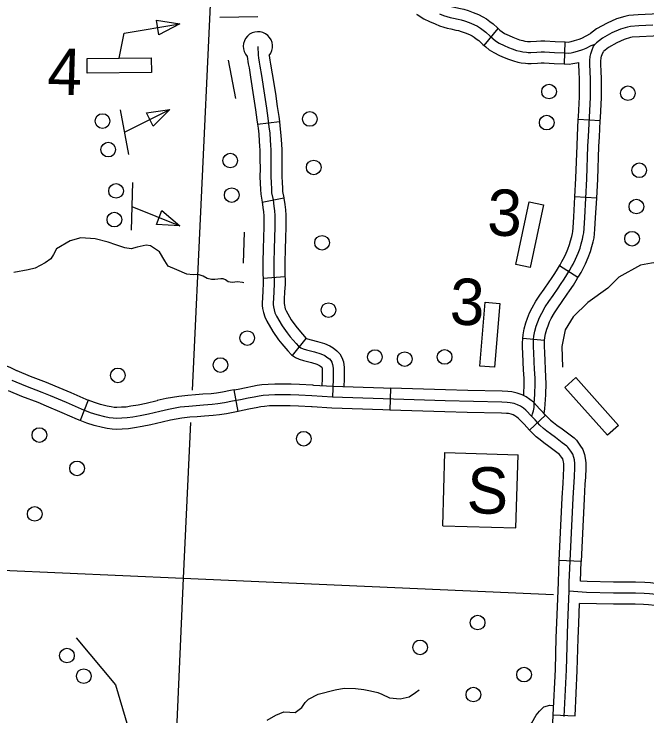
# Model space of a CAD drawing. Extents: x 653372 to 905732, y 627442 to 787275.
# Drawn here: x 709737 to 714058, y 756322 to 761114 of the extents above; entities that cross this region are included whole.
import ezdxf

# ---------------------------------------------------------------- set-up
doc = ezdxf.new("R2010")
doc.units = 0
for name, color, linetype in [('31', 7, 'Continuous'), ('32', 7, 'Continuous'), ('35', 7, 'Continuous'), ('45', 7, 'Continuous'), ('5', 7, 'Continuous'), ('56', 7, 'Continuous'), ('57', 7, 'Continuous')]:
    doc.layers.add(name, color=color, linetype=linetype)

msp = doc.modelspace()

# ---------------------------------------------------------------- linework, layer by layer
at = {"layer": '31'}
for p, q in [((711266.8, 758401), (711239.4, 758548.5)), ((711239.4, 758548.5), (711239.4, 758548.5)), ((712307.2, 758560), (712302.7, 758410)), ((710243, 758479), (710188.8, 758339.2)), ((713255.9, 758274.1), (713366.1, 758375.9)), ((713609.4, 757377.6), (713459.5, 757384.2)), ((713417.4, 756329.5), (713567.3, 756322.1))]:
    msp.add_line(p, q, dxfattribs=at)
for points in [[(709238.7, 758833), (709264.6, 758827.5), (709357.5, 758806.8), (709445.2, 758785.6), (709488.3, 758774.9), (709560.8, 758756.9), (709619.7, 758738.5), (709668.7, 758718.9), (709708.8, 758703.1), (709754.5, 758681.5), (709757.4, 758680.3)], [(709757.4, 758680.3), (709846.6, 758642.6), (709957.7, 758600.6), (710016.4, 758575.5), (710124.4, 758530.3), (710227.3, 758485.1), (710243, 758479)], [(710198.6, 758415.8), (710094.8, 758461.4), (709987.2, 758506.4), (709929.6, 758531), (709818.8, 758573), (709723.9, 758613.1)], [(711239.4, 758548.5), (711267.8, 758553.7), (711321.5, 758565.4), (711364.1, 758573.3), (711397.8, 758579.5), (711429.4, 758584.3), (711471.6, 758587.9), (711516.7, 758590), (711584.8, 758589.9), (711628.1, 758588.6), (711685.9, 758586.2), (711775, 758581.6), (711781.7, 758581.3)], [(711781.7, 758581.3), (711914.2, 758573.7), (712259.6, 758561.4), (712307.2, 758560)], [(710188.8, 758339.2), (710170, 758346.4), (710065.3, 758392.4), (709958, 758437.3), (709901.6, 758461.4), (709790.9, 758503.3), (709699, 758542.1)], [(713540.8, 757524), (713554.5, 757808.3), (713562.7, 757957), (713565.1, 758015.6), (713564.8, 758046.6), (713562.3, 758069.5), (713558.4, 758086.1), (713550.8, 758108.5), (713537.5, 758129.9), (713518.9, 758156), (713510.7, 758164.3), (713479.7, 758187.4), (713433.9, 758222.3), (713399.1, 758247.4), (713373.7, 758266.6), (713350.8, 758284.4), (713327.4, 758307.3), (713293.7, 758343.8), (713273, 758365.9), (713231.6, 758409), (713214.3, 758422.8), (713194.4, 758436.1), (713175.1, 758446.2), (713152, 758454.3), (713124.2, 758460.4), (713103.3, 758461.7), (713066.6, 758463.4), (712680.2, 758473.7), (712257.2, 758486.4), (711910.7, 758498.8), (711771, 758506.7), (711682.4, 758511.3), (711625.4, 758513.6), (711583.7, 758514.9), (711518.4, 758515), (711476.5, 758513), (711438.2, 758509.8), (711410.2, 758505.5), (711377.7, 758499.5), (711336.3, 758491.9), (711282.7, 758480.2), (711229.8, 758470.4), (711175, 758459.4), (711129.1, 758451.9), (711090.4, 758447.3), (711031.3, 758443.4), (710981.5, 758439.2), (710930.7, 758435.6), (710872.2, 758429.1), (710790.7, 758415.1), (710732, 758401.7), (710655.4, 758383.1), (710598, 758370.8), (710547.7, 758362.2), (710510.5, 758356.3), (710473, 758354.3), (710438.8, 758353.4), (710413.5, 758354.2), (710387, 758358.2), (710357.4, 758364.1), (710305.9, 758376.7), (710260.1, 758392), (710198.6, 758415.8)], [(711239.4, 758548.5), (711215.6, 758544), (711161.5, 758533.1), (711118.7, 758526.1), (711083.5, 758522), (711025.7, 758518.2), (710975.7, 758514), (710924, 758510.3), (710861.7, 758503.4), (710776, 758488.7), (710714.8, 758474.7), (710713.3, 758474.3)], [(712834.7, 758544.6), (712682.3, 758548.7), (712307.2, 758560)], [(713366.1, 758375.9), (713348.6, 758394.8), (713327.5, 758417.5), (713282.3, 758464.5), (713258.6, 758483.4), (713232.7, 758500.7), (713205, 758515.2), (713172.6, 758526.5), (713134.6, 758534.9), (713107.4, 758536.6), (713069.4, 758538.3), (712834.7, 758544.6)], [(710713.3, 758474.3), (710638.8, 758456.2), (710583.9, 758444.5), (710535.6, 758436.2), (710502.6, 758431), (710470, 758429.3), (710439, 758428.5), (710420.2, 758429), (710399.9, 758432), (710373.7, 758437.3), (710326.7, 758448.8), (710285.5, 758462.5), (710243, 758479)], [(711773.2, 758431.5), (711766.9, 758431.8), (711678.9, 758436.4), (711622.8, 758438.7), (711582.5, 758439.9), (711520.1, 758440), (711481.4, 758438.2), (711447, 758435.2), (711422.6, 758431.6), (711391.3, 758425.8), (711351.1, 758418.4), (711297.5, 758406.7), (711266.8, 758401)], [(712302.7, 758410), (712254.7, 758411.5), (711907.3, 758423.9), (711773.2, 758431.5)], [(711266.8, 758401), (711244, 758396.7), (711188.4, 758385.6), (711139.6, 758377.6), (711097.2, 758372.6), (711037, 758368.6), (710987.3, 758364.4), (710937.5, 758360.9), (710882.7, 758354.9), (710805.5, 758341.6), (710749.2, 758328.7), (710748.8, 758328.6)], [(712830.7, 758394.7), (712678.1, 758398.8), (712302.7, 758410)], [(713255.9, 758274.1), (713238.7, 758292.7), (713218.6, 758314.4), (713181, 758353.5), (713170, 758362.2), (713156.2, 758371.5), (713145.2, 758377.2), (713131.5, 758382), (713113.8, 758385.9), (713099.3, 758386.8), (713063.9, 758388.4), (712830.7, 758394.7)], [(713366.1, 758375.9), (713381.2, 758359.5), (713400.2, 758341), (713419.3, 758326.1), (713443.7, 758307.8), (713478.6, 758282.6), (713524.9, 758247.2), (713559.9, 758221.1), (713576.4, 758204.6), (713599.9, 758171.5), (713619.1, 758140.8), (713630.6, 758106.8), (713636.4, 758082.3), (713639.8, 758051.1), (713640.2, 758014.5), (713637.7, 757953.4), (713634.9, 757904.1)], [(710748.8, 758328.6), (710672.1, 758309.9), (710612.2, 758297.2), (710559.9, 758288.2), (710518.4, 758281.7), (710476, 758279.4), (710438.6, 758278.4), (710406.8, 758279.4), (710374, 758284.3), (710341.1, 758290.9), (710285.1, 758304.5), (710234.6, 758321.4), (710188.8, 758339.2)], [(713485.1, 757912.4), (713487.8, 757960.6), (713490.1, 758016.7), (713489.8, 758042.2), (713488.3, 758056.8), (713486.2, 758065.4), (713482.6, 758076.3), (713475.1, 758088.2), (713461.4, 758107.4), (713434.5, 758127.5), (713389.1, 758162.1), (713354.6, 758187.1), (713328.1, 758207), (713301.4, 758227.8), (713273.6, 758255), (713255.9, 758274.1)], [(713459.5, 757384.2), (713465.9, 757527.5), (713479.6, 757812.2), (713485.1, 757912.4)], [(713634.9, 757904.1), (713629.4, 757804.4), (713615.7, 757520.5), (713609.4, 757377.6)], [(713492, 756318.9), (713507.7, 756636.1), (713517, 756958.2), (713525.8, 757173.6), (713528, 757235.1), (713540.8, 757524)], [(713439, 756855.5), (713442.1, 756960.8), (713450.9, 757176.4), (713453.1, 757238.1), (713459.5, 757384.2)], [(713603.5, 757242.8), (713609.4, 757377.6)], [(713956.8, 757235.6), (713830.6, 757236), (713649.5, 757239.3), (713603.5, 757242.8)], [(714490.5, 757157.5), (714444.3, 757165.6), (714362.8, 757185.2), (714303.2, 757198.7), (714246.7, 757208.7), (714205.4, 757215.3), (714174.6, 757219.2), (714129.8, 757225), (714083.2, 757230.6), (714042.7, 757233.7), (713980.6, 757235.5), (713956.8, 757235.6)], [(714558.8, 757077), (714532.7, 757075.4), (714503.3, 757079.1), (714429, 757092.1), (714345.7, 757112.2), (714288.4, 757125.2), (714234.3, 757134.8), (714194.9, 757141), (714165, 757144.8), (714120.5, 757150.6), (714076, 757155.9), (714038.7, 757158.7), (713979.3, 757160.5), (713829.8, 757161), (713646, 757164.3), (713525.8, 757173.6)], [(713588.9, 756851.1), (713592, 756955.5), (713597.5, 757090.1)], [(713956.2, 757085.6), (713829, 757086.1), (713597.5, 757090.1)], [(714464.6, 757009.8), (714413.8, 757018.6), (714328.6, 757039.1), (714273.5, 757051.7), (714221.9, 757060.8), (714184.4, 757066.8), (714155.5, 757070.4), (714111.2, 757076.2), (714068.7, 757081.3), (714034.8, 757083.8), (713978.1, 757085.5), (713956.2, 757085.6)], [(713417.4, 756329.5), (713432.7, 756639), (713439, 756855.5)], [(713567.3, 756322.1), (713582.6, 756633.2), (713588.9, 756851.1)], [(713323.6, 755939.5), (713359.7, 755951.2), (713384.7, 755962.7), (713392, 755969.6), (713393.6, 755972.4), (713398.1, 755990.4), (713405.4, 756060.5), (713409, 756157.1), (713417.1, 756322.6), (713417.4, 756329.5)]]:
    msp.add_lwpolyline(points, dxfattribs=at)
at = {"layer": '32'}
for p, q in [((712947.1, 760898.2), (713042.3, 761014.2)), ((713495.1, 760773.8), (713499.6, 760923.7)), ((713738.9, 760385.5), (713589.1, 760393)), ((711399.9, 760361.3), (711548.7, 760380.2)), ((711431.9, 759830.5), (711579.2, 759858.7)), ((713715.3, 759857.7), (713565.5, 759866)), ((713587.1, 759314.6), (713460.9, 759395.6)), ((711437.2, 759311.6), (711586.7, 759323.3)), ((711638.9, 758782.9), (711730.9, 758899.6)), ((713359.2, 758885.3), (713209.8, 758898.4))]:
    msp.add_line(p, q, dxfattribs=at)
for points in [[(712562.1, 761242.2), (712567.6, 761238.9), (712609.2, 761212.3), (712635.9, 761198.6), (712668.7, 761185.2), (712694.5, 761174.8), (712713.2, 761168.6), (712731.8, 761163.8), (712753.8, 761158.4), (712784.4, 761151.2), (712807.9, 761146.4), (712836.3, 761138.2), (712871.2, 761125.6), (712908, 761110.8), (712936.8, 761096), (712962.6, 761080.7), (712984.9, 761063.9), (713007.1, 761046.2), (713036.6, 761018.8), (713042.3, 761014.2)], [(712484.2, 761114), (712488.2, 761111.6), (712534.4, 761082), (712573.2, 761062.1), (712612.6, 761046.1), (712642.8, 761034), (712670.6, 761024.6), (712695.2, 761018.3), (712718.7, 761012.5), (712752.1, 761004.7), (712771.9, 761000.6), (712790, 760995.4), (712817.8, 760985.4), (712845.6, 760974.2), (712864.1, 760964.7), (712879, 760955.8), (712893, 760945.3), (712909.2, 760932.4), (712938, 760905.7), (712947.1, 760898.2)], [(712640.6, 761115.6), (712668.7, 761104.4), (712691.9, 761096.6), (712713.5, 761091.1), (712736.3, 761085.5), (712768.2, 761078), (712789.9, 761073.5), (712813.2, 761066.8), (712844.5, 761055.5), (712876.8, 761042.5), (712900.4, 761030.3), (712920.8, 761018.3), (712938.9, 761004.6), (712958.1, 760989.3), (712987.3, 760962.3), (713005.9, 760947), (713025.1, 760931.1), (713049.2, 760916.2), (713084.1, 760898.8), (713112.3, 760885.9), (713138.7, 760875.9), (713167.3, 760865.7), (713193.3, 760859.5), (713210.7, 760855.7), (713235.1, 760852.8), (713247.1, 760851.9), (713265.7, 760851.9), (713307, 760854.4), (713334.9, 760855.2), (713357.8, 760855.1), (713426.9, 760851.4), (713495.6, 760848.8), (713523.4, 760847.9), (713540.9, 760849.6), (713559, 760853.4), (713584.9, 760860.8), (713619.6, 760872.3), (713643.8, 760881.4), (713676.5, 760898.5), (713703.6, 760909.4)], [(714160, 761116.2), (714148.1, 761115.3), (714094.6, 761113.8), (713998.6, 761109.3), (713934.3, 761104.2), (713906.3, 761097.7), (713849.9, 761080.4), (713785.7, 761051.8), (713713.3, 761011.9), (713672.7, 760981)], [(713042.3, 761014.2), (713053.6, 761004.8), (713068.9, 760992.2), (713085.7, 760981.8), (713116.4, 760966.5), (713141.3, 760955.2), (713164.6, 760946.3), (713188.7, 760937.7), (713210.1, 760932.6), (713223.2, 760929.7), (713242.4, 760927.4), (713250, 760926.9), (713263.3, 760926.9), (713303.6, 760929.4), (713334, 760930.2), (713360, 760930.1), (713430.4, 760926.3), (713498.1, 760923.7), (713499.6, 760923.7)], [(714097.5, 761038.9), (714003.3, 761034.4), (713945.8, 761029.9), (713925.8, 761025.2), (713876.2, 761010), (713819.1, 760984.6), (713754.3, 760948.9), (713712.4, 760917), (713703.6, 760909.4)], [(713499.6, 760923.7), (713521, 760923), (713529.6, 760923.9), (713540.9, 760926.3), (713562.7, 760932.5), (713594.6, 760943.1), (713613.2, 760950.1), (713672.7, 760981)], [(714170.7, 760966.5), (714155.5, 760965.5), (714100.3, 760963.9), (714008.1, 760959.5), (713957.2, 760955.5), (713945.3, 760952.8), (713902.6, 760939.6), (713852.5, 760917.3), (713795.3, 760885.9), (713760.5, 760859.3)], [(713273, 758365.9), (713277.3, 758384.1), (713282.4, 758404.6), (713286.9, 758428.1), (713288.5, 758455), (713291.8, 758517.1), (713294.9, 758593.5), (713293.7, 758629), (713290.3, 758690.2), (713287.3, 758740.2), (713285, 758802.6), (713283.1, 758839.3), (713283.3, 758866.3), (713284.4, 758891), (713286.5, 758915), (713292.8, 758948.5), (713302.5, 758983.6), (713311.9, 759011.8), (713324.1, 759043.3), (713339.2, 759072), (713363, 759114.4), (713388.8, 759150.8), (713418.2, 759193), (713451.8, 759243.3), (713467.5, 759266.6), (713492.6, 759303.7), (713510.4, 759333.9), (713529.2, 759363.3), (713542.7, 759387.3), (713553.4, 759406.1), (713569.1, 759439.5), (713587.2, 759480.6), (713601, 759516.1), (713609.4, 759545.5), (713617.5, 759577.5), (713623.1, 759601.1), (713626.3, 759621.3), (713628.3, 759649.7), (713632.8, 759726), (713647.5, 759989.9), (713655.3, 760213.1), (713658.4, 760279), (713664.9, 760408.2), (713671.7, 760546.7), (713672.3, 760665.7), (713670.4, 760726.5), (713668.5, 760764.4), (713668.7, 760796.2), (713671.3, 760824.8), (713674.4, 760843.1), (713680.5, 760863.7), (713693.9, 760894.1), (713703.6, 760909.4)], [(711402.4, 760893.5), (711404.3, 760833.1), (711406.7, 760813.9), (711410.3, 760786.5), (711415.3, 760758.4), (711425.9, 760693.9), (711446.9, 760559.2), (711459.8, 760471.9), (711470.2, 760403), (711477.8, 760342.9), (711482.5, 760300.8), (711485.4, 760252.1), (711488.1, 760218.1), (711490.1, 760187.1), (711489.6, 760120.8), (711491.4, 760059.6), (711491.2, 760004.3), (711492.2, 759961.5), (711494.6, 759920.9), (711496, 759894.3), (711505.6, 759844.5), (711511, 759803.1), (711515.1, 759769.8), (711517.1, 759738.1), (711517.5, 759702.7), (711516.8, 759654.8), (711515.7, 759592.2), (711513.8, 759504.6), (711511.4, 759425.8), (711511.2, 759367.6), (711510.3, 759338.7), (711513, 759304.7), (711513.4, 759269.4), (711509.8, 759223), (711507.5, 759170.8), (711506, 759145.8), (711507, 759131), (711508.7, 759114.7), (711512.5, 759094), (711518.6, 759074.6), (711529, 759052.2), (711566.8, 758986.2), (711601.4, 758936.6), (711623.3, 758910.5), (711662.4, 758864.4), (711680.3, 758845.5), (711694.7, 758835.4), (711710.7, 758829.1), (711734.8, 758821), (711788.1, 758806.8), (711831.2, 758793.8), (711858.1, 758781.9), (711872.5, 758772.6), (711889.8, 758759.6), (711900.5, 758748.2), (711906.9, 758737.7), (711912.3, 758722.1), (711915.2, 758696.9), (711915.2, 758622.5), (711910.7, 758498.8)], [(712947.1, 760898.2), (712958.2, 760889.1), (712981.2, 760870), (713012.6, 760850.6), (713051.8, 760831.1), (713083.4, 760816.7), (713112.9, 760805.5), (713146, 760793.7), (713176.6, 760786.4), (713198.2, 760781.7), (713227.9, 760778.1), (713244.3, 760776.9), (713268, 760776.9), (713310.4, 760779.5), (713335.7, 760780.2), (713355.5, 760780.1), (713423.5, 760776.5), (713493, 760773.8), (713495.1, 760773.8)], [(711329.6, 760825), (711336.1, 760775), (711341.4, 760745.7), (711351.9, 760682.1), (711372.8, 760548), (711385.6, 760460.8), (711395.9, 760392.6), (711399.9, 760361.3)], [(711480.1, 760830.5), (711484.4, 760798), (711489.2, 760771.1), (711500, 760705.8), (711521.1, 760570.4), (711533.9, 760482.9), (711544.5, 760413.4), (711548.7, 760380.2)], [(713738.9, 760385.5), (713739.8, 760404.5), (713746.7, 760544.6), (713747.3, 760666.7), (713745.3, 760729.5), (713743.5, 760766), (713743.7, 760792.7), (713745.7, 760815.1), (713747.6, 760826), (713751.1, 760837.9), (713760.5, 760859.3)], [(713495.1, 760773.8), (713525.8, 760772.8), (713552.2, 760775.3), (713593.6, 760784.1)], [(713589.1, 760393), (713590, 760411.9), (713596.7, 760548.7), (713597.3, 760664.7), (713595.4, 760723.5), (713593.5, 760762.8), (713593.6, 760784.1)], [(713565.5, 759866), (713572.6, 759993.3), (713580.4, 760216.2), (713583.5, 760282.7), (713589.1, 760393)], [(713715.3, 759857.7), (713722.4, 759986.5), (713730.3, 760210.1), (713733.3, 760275.4), (713738.9, 760385.5)], [(711399.9, 760361.3), (711403.4, 760334.1), (711407.7, 760294.4), (711410.6, 760246.9), (711413.3, 760212.7), (711415.1, 760184.9), (711414.6, 760119.9), (711416.4, 760058.5), (711416.2, 760003.6), (711417.2, 759958.4), (711419.8, 759916.7), (711421.4, 759885.2), (711431.9, 759830.5)], [(711548.7, 760380.2), (711552.3, 760351.8), (711557.2, 760307.2), (711560.2, 760257.3), (711562.9, 760223.5), (711565.1, 760189.2), (711564.6, 760121.6), (711566.4, 760060.6), (711566.2, 760005), (711567.1, 759964.6), (711569.5, 759925.2), (711570.7, 759903.4), (711579.2, 759858.7)], [(711579.1, 759859.2), (711579.6, 759856.7), (711585.4, 759812.6), (711589.9, 759776.8), (711592.1, 759740.9), (711592.6, 759702.6), (711591.8, 759653.6), (711590.7, 759590.7), (711588.8, 759502.6), (711586.4, 759424.5), (711586.2, 759366.3), (711585.4, 759340.5), (711586.7, 759323.3)], [(713460.9, 759395.6), (713464.9, 759401.9), (713477.4, 759424.1), (713486.8, 759440.6), (713500.9, 759470.6), (713517.9, 759509.3), (713529.9, 759540), (713537, 759565), (713544.6, 759595.3), (713549.5, 759615.7), (713551.7, 759629.8), (713553.4, 759654.5), (713557.9, 759730.3), (713565.5, 759866)], [(713587.1, 759314.6), (713593.5, 759324.7), (713608, 759350.4), (713620, 759371.5), (713637.4, 759408.4), (713656.5, 759451.9), (713672.2, 759492.2), (713681.9, 759526), (713690.4, 759559.7), (713696.7, 759586.5), (713700.9, 759612.7), (713703.1, 759644.9), (713707.7, 759721.7), (713715.3, 759857.7)], [(711431.6, 759832.4), (711436.6, 759793.6), (711440.4, 759762.8), (711442.2, 759735.3), (711442.5, 759702.8), (711441.9, 759656), (711440.7, 759593.7), (711438.8, 759506.5), (711436.4, 759427.1), (711436.2, 759368.9), (711435.2, 759336.9), (711437.2, 759311.5)], [(713209.8, 758898.4), (713212.1, 758925.1), (713219.6, 758965.4), (713230.7, 759005.5), (713241.4, 759037.2), (713255.7, 759074.3), (713273.3, 759107.8), (713299.5, 759154.6), (713327.4, 759193.9), (713356.2, 759235.3), (713389.5, 759285.1), (713405.3, 759308.5), (713429.1, 759343.7), (713446.5, 759373.2), (713460.9, 759395.6)], [(711437.2, 759311.6), (711438, 759301.4), (711438.3, 759271.8), (711434.9, 759227.6), (711432.6, 759174.7), (711430.8, 759145.4), (711432.3, 759124.4), (711434.4, 759104), (711439.6, 759076), (711448.5, 759047.6), (711462.3, 759017.8), (711503.3, 758946.1), (711541.8, 758890.9), (711566, 758862.1), (711606.5, 758814.4), (711631, 758788.3), (711638.9, 758782.8)], [(711586.7, 759323.3), (711587.9, 759308.1), (711588.4, 759266.9), (711584.6, 759218.5), (711582.4, 759166.9), (711581.1, 759146.2), (711581.7, 759137.6), (711583, 759125.5), (711585.5, 759112), (711588.7, 759101.7), (711595.7, 759086.7), (711630.2, 759026.4), (711660.9, 758982.3), (711680.6, 758959), (711730.9, 758899.6)], [(713359.2, 758885.3), (713360.9, 758904.8), (713365.9, 758931.6), (713374.2, 758961.6), (713382.5, 758986.3), (713392.5, 759012.2), (713405.1, 759036.3), (713426.4, 759074.3), (713450.1, 759107.6), (713480.1, 759150.7), (713514.1, 759201.5), (713529.7, 759224.6), (713556, 759263.6), (713574.3, 759294.6), (713587.1, 759314.6)], [(711730.9, 758899.6), (711808.6, 758879), (711857.3, 758864.2), (711893.7, 758848.2), (711915.5, 758834.2), (711940.1, 758815.6), (711960.7, 758793.7), (711975.2, 758769.6), (711985.8, 758738.9), (711990.2, 758701.3), (711990.2, 758621.1), (711988.4, 758571.1)], [(713216.5, 758511.6), (713219.8, 758593.8), (713218.7, 758625.7), (713215.4, 758685.9), (713212.4, 758736.6), (713210.1, 758799.3), (713208.1, 758837.7), (713208.3, 758868.3), (713209.6, 758896), (713209.8, 758898.4)], [(713355.5, 758387.4), (713361.5, 758418.9), (713363.3, 758450.9), (713366.7, 758513.6), (713369.9, 758593.2), (713368.6, 758632.4), (713365.1, 758694.5), (713362.2, 758743.8), (713360, 758805.8), (713358.1, 758841), (713358.3, 758864.4), (713359.3, 758886.1), (713359.2, 758885.3)], [(711638.9, 758782.9), (711659, 758768.9), (711684.9, 758758.6), (711713.2, 758749.1), (711767.6, 758734.7), (711805.1, 758723.3), (711822.5, 758715.6), (711829.6, 758711), (711838.9, 758704.1), (711840.2, 758692.6), (711840.2, 758623.8), (711838.5, 758578)]]:
    msp.add_lwpolyline(points, dxfattribs=at)
msp.add_arc((711402.4, 760893.5), 100, 320.9907, 223.2344, dxfattribs=at)
at = {"layer": '35'}
for points in [[(711305.9, 759278.6), (711296.9, 759281), (711262.8, 759286.7), (711225.3, 759281.6), (711199, 759285.5), (711180.7, 759298.5), (711165.3, 759305.2), (711148.2, 759305.7), (711109.2, 759302.2), (711085.8, 759301.4), (711056.4, 759308.5), (711027.4, 759324.9), (710993.4, 759335.3), (710959.1, 759333.2), (710917.3, 759339.1), (710849.6, 759367.6), (710789.7, 759392.8), (710767.4, 759429.3), (710730.4, 759491.1), (710669.3, 759530.6), (710639.9, 759536.2), (710577.2, 759522.2), (710537.9, 759510.9), (710493, 759518.5), (710432.9, 759537.4), (710379.6, 759556.2), (710290.6, 759579.8), (710193.7, 759585.1), (710121.5, 759565.5), (710028, 759510.7), (710006.6, 759472.4), (709988.6, 759443.3), (709950.5, 759416.4), (709880.9, 759379.6), (709833, 759367.8), (709735.2, 759349.7)], [(714882.6, 759071.4), (714741.9, 759131.5), (714645.6, 759185.6), (714523.2, 759279.3), (714423.9, 759360.6), (714331.5, 759410.3), (714245.9, 759428.6), (714179.3, 759426.7), (714089, 759413.7), (714014.2, 759400.3), (713867, 759318.6), (713790.3, 759242.6), (713654.4, 759144.9), (713553.6, 759046.2), (713500, 758957.8), (713477.1, 758844.9), (713480.7, 758703.9)], [(711464.9, 756292.3), (711523.8, 756326.4), (711578.4, 756350.7), (711620.2, 756347.5), (711656.1, 756346.4), (711701, 756379), (711724, 756414.3), (711746.7, 756437.5), (711813.6, 756471.5), (711929.8, 756499.8), (711990, 756512), (712067.8, 756509.6), (712125.5, 756501.9), (712171.2, 756494.6), (712220.7, 756481.1), (712248.3, 756470.3), (712299.5, 756446.8), (712374.3, 756438.6), (712434.6, 756452.7), (712477.4, 756481.4), (712503.3, 756499.6)]]:
    msp.add_lwpolyline(points, dxfattribs=at)
at = {"layer": '45'}
msp.add_lwpolyline([(713152.3, 756239.7), (713231.6, 756234.6), (713232.5, 756234.8), (713234.1, 756235.5), (713242.5, 756242), (713271.9, 756274.8), (713300.8, 756328.5), (713325.3, 756355.6), (713354.7, 756384.7), (713394.8, 756395.8), (713420.7, 756394.4)], dxfattribs=at)
at = {"layer": '5'}
for points in [[(711075.2, 761176.6), (710952.7, 758545.9)], [(710942.4, 758325.4), (710892.9, 757262.5)], [(709657.1, 757318), (710892.9, 757262.5)], [(710892.9, 757262.5), (710750.3, 754053.8)], [(710892.9, 757262.5), (713419.1, 757150.9)]]:
    msp.add_lwpolyline(points, dxfattribs=at)
at = {"layer": '56'}
for p, q in [((710709.2, 761072.2), (710868.7, 761048)), ((710726.6, 760971.7), (710709.2, 761072.2)), ((710868.7, 761048), (710726.6, 760971.7)), ((710640.9, 760439), (710800.7, 760461.3)), ((710686.2, 760347.6), (710640.9, 760439)), ((710800.7, 760461.3), (710686.2, 760347.6)), ((710708.9, 759678.3), (710747, 759773)), ((710747, 759773), (710869.9, 759668.5)), ((710869.9, 759668.5), (710708.9, 759678.3))]:
    msp.add_line(p, q, dxfattribs=at)
for points in [[(711142.7, 761093.6), (711402.3, 761096.8)], [(710455.1, 760812.4), (710488.5, 760982.4), (710868.7, 761048)], [(711199.8, 760798.5), (711249.2, 760537.4)], [(710461.8, 760459.9), (710519.3, 760155.3)], [(710490.6, 760307.6), (710800.7, 760461.3)], [(710545.8, 759963.6), (710536.1, 759638.3)], [(710540.9, 759800.9), (710869.9, 759668.5)], [(711307.5, 759623.9), (711301.2, 759412.9)], [(710162.4, 756855), (710429.3, 756534.3), (710688, 755665.3)]]:
    msp.add_lwpolyline(points, dxfattribs=at)
for points in [[(710237.6, 760709.7), (710236.4, 760809.7), (710673.8, 760815.1), (710675.1, 760715.1)], [(713253.4, 759831.3), (713351.2, 759810.7), (713261.5, 759382.6), (713163.6, 759403.1)], [(712953.9, 759146.6), (713053.6, 759138.3), (713017.5, 758702.3), (712917.8, 758710.5)], [(713497.7, 758565.5), (713572.5, 758631.9), (713863, 758304.8), (713788.3, 758238.4)]]:
    msp.add_lwpolyline(points, close=True, dxfattribs=at)
for centre in [(713389.7, 760584.6), (713927.8, 760573.5), (710341.3, 760383.5), (711756.5, 760397.6), (713373.7, 760372.6), (710380.2, 760188.3), (711213.2, 760113.7), (711783, 760066.6), (714005.1, 760047.3), (710433.5, 759906.7), (711223.5, 759877.9), (713985.6, 759799.9), (710422.1, 759710.6), (713956.2, 759580.4), (711840, 759552.4), (711884, 759092.9), (711329.1, 758901.5), (712200.5, 758772.3), (712404.2, 758758.4), (712676.5, 758773), (711146.2, 758717.7), (710446, 758647.1), (709910.5, 758240), (711715.2, 758214.6), (710167.4, 758012.4), (709878.3, 757701.7), (712902.1, 756959.9), (712509.2, 756790.4), (710098.7, 756734.4), (713219.1, 756604.5), (710213.4, 756593.8), (712872.9, 756468.1)]:
    msp.add_circle(centre, 50, dxfattribs=at)
at = {"layer": '57'}
for p, q in [((712664, 757620.8), (712679, 758120.6)), ((712679, 758120.6), (713178.8, 758105.6)), ((713163.8, 757605.8), (713178.8, 758105.6)), ((712664, 757620.8), (713163.8, 757605.8))]:
    msp.add_line(p, q, dxfattribs=at)

# ---------------------------------------------------------------- texts
at = {"layer": '56'}
for s, p in [('4', (709962.1, 760565.9)), ('3', (712964.5, 759602.8)), ('3', (712708.8, 758994.5))]:
    msp.add_text(s, height=316.8, rotation=358.28, dxfattribs=at).set_placement(p)
at = {"layer": '57'}
msp.add_text('S', height=316.8, rotation=358.28, dxfattribs=at).set_placement((712824.5, 757707.6))

doc.saveas('drawing.dxf')
